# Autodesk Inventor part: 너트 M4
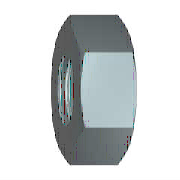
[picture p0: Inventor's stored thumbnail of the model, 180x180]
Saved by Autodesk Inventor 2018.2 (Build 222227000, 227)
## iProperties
Created: 2012-02
Part Number: 너트 M4
Material: 강철, 연강
Description: 6각 너트 및 6각 가는 너트 - 스타일 1
Document SubType Name: Modeling
Standard: KS B 1012
Designer: mduedu
Standards Organization: KS
Language: ko-KR
Size Designation: A M4
Categories: <MemberInstance><Categories><Category DisplayName="조임쇠" InternalName="e4da775c-781d-43d5-af7c-5136215cf5a6" Mnemonic="FSTN"><Category DisplayName="너트" InternalN
Density: 7.86 g/cm^3
Mass: 0.846697 g
Surface Area: 1.71448 cm^2
Volume: 0.107722 cm^3
Appearance: 강철
IsCustomPart: 0
Author: mduedu
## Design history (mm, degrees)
sketch "스케치1"
  geometry: L1 (-4.041, 0)-(-2.021, 3.5); L2 (-2.021, 3.5)-(2.021, 3.5); L3 (2.021, 3.5)-(4.041, 0); L4 (4.041, 0)-(2.021, -3.5); L5 (2.021, -3.5)-(-2.021, -3.5); L6 (-2.021, -3.5)-(-4.041, 0); 2 further points
  constraints: 12 end point, 1 coincident, 1 horizontal, 11 other
  dimensions: "d0" = 8.0829 distance of L3.end L1.start (= 1.1547 x SW)
extrude "본체" new body sketch "스케치1" distance "d1" = 3.2 (= KOH); taper "d2" = 0 deg
sketch "스케치2"
  geometry: L1 (0, 2.021)-(0, 4.041) reference; L2 (0, 4.041)-(3.2, 4.041) reference; L3 (3.2, 2.021)-(3.2, 4.041) reference; L4 (-0.64, 0)-(3.84, 0) reference; L5 (0.313, 4.041)-(0, 3.5); L6 (2.887, 4.041)-(3.2, 3.5)
  constraints: 4 end point, 4 point on line
  dimensions: "d3" = 30 deg angle of L1 L5 (= ANG1); "d4" = 30 deg angle of L3 L6 (= ANG2); "d5" = 7 diameter of L5.end L4 (= SW0); "d6" = 7 diameter of L6.end L4 (= SW01)
revolve "모따기1" sketch "스케치2" stored, may be unused: angle "d7" = 90 deg
sketch "스케치3"
  geometry: A1 r 3.5 centre (0, 0) between (-1.75, -3.031) and (1.75, -3.031) reference; 1 further point
  constraints: 1 coincident
hole "스레드" sketch "스케치3" at (0, 0) diameter "d25" = 3.242; stored, may be unused: countersink angle "d29" = 82 deg, drill point angle "d31" = 118 deg; dims "d26" = 6, "d27" = 4, "d28" = 2, "d30" = 8
workaxis "Work Axis1"
workplane "Work Plane1"
body "Solid1"
chamfer "모따기2" distance "d8" = 0.37889 (= -0.5 x GD1 + 0.5 x NND); stored, may be unused: angle "d9" = 30 deg, second distance "d40" = 0.37889 (= -0.5 x GD1 + 0.5 x NND)
chamfer "모따기3" distance "d10" = 0.37889 (= -0.5 x GD1 + 0.5 x NND); stored, may be unused: angle "d11" = 30 deg, second distance "d41" = 0.37889 (= -0.5 x GD1 + 0.5 x NND)
other parameters: "ANG1" = 30 deg [user parameter; used in 1 equation term], "ANG2" = 30 deg [user parameter; used in 1 equation term], "NND" = 4 [user parameter; used in 4 equation terms], "KOH" = 3.2 [user parameter; used in 1 equation term], "SW" = 7 [user parameter; used in 4 equation terms], "SW0" = 7 (= SW) [user parameter; used in 1 equation term], "SW01" = 7 (= SW) [user parameter; used in 1 equation term], "GD1" = 3.24223 (computed from THREADDIA, PTC, TOA) [user parameter; used in 4 equation terms], "d13" = 0, "d14" = 0, "d39" = 0, "d42" = 0, "GUL" = 0.37889 (= 0.541266 x PTC) [user parameter], "TPU" = 14.28571 (computed from PTC) [user parameter], "THREADDIA" = 4 [user parameter; used in 1 equation term], "TOA" = 30 deg [user parameter; used in 1 equation term], "PTC" = 0.7 [user parameter; used in 4 equation terms], "E0" = 8.085 (= 1.155 x SW) [user parameter], "GAL" = 0.37889 (= 0.541266 x PTC) [user parameter]
